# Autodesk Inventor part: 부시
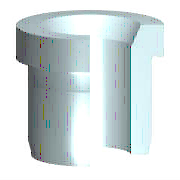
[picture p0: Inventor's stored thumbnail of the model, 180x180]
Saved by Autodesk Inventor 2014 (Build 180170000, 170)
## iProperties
IsCustomPart: 1
Created: 2009-02
Part Number: 부시
Material: 강, 연강
Description: 압력 맞춤 부시 - 머리 있는 유형
Document SubType Name: Modeling
Standard: ISO 4247
Designer: KYOUNG IL JANG
Standard Revision: 1판 1977-12-15
Standards Organization: ISO
Language: ko-KR
Size Designation: 15
Categories: <MemberInstance><Categories><Category DisplayName="기타 부품" InternalName="5aa15e00-363f-49f2-933f-16f664388e3f" Mnemonic="OTHER"><Category DisplayName="드릴 부싱" Int
Density: 7.86 g/cm^3
Mass: 62.5871 g
Surface Area: 38.4072 cm^2
Volume: 7.96273 cm^3
Appearance: 강철
Author: KYOUNG IL JANG
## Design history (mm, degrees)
revolve "본체" stored, may be unused: angle "d12" = 90 deg
body "Solid1"
chamfer "모따기1" distance "d13" = 2 (= KAH); stored, may be unused: angle "d14" = 30 deg (= SEWI), second distance "d19" = 2 (= KAH)
chamfer "모따기2" distance "d15" = 1.5 (= PHH); stored, may be unused: angle "d16" = 15 deg (= ANG), second distance "d20" = 1.5 (= PHH)
sketch "스케치1"
  geometry: L1 (2.5, 11)-(24, 11); L2 (24, 11)-(24, 6); L3 (24, 6)-(-4, 6); L4 (-4, 6)-(-4, 13); L5 (-4, 13)-(0, 13); L6 (0, 13)-(0, 12.304); L7 (-2.619, 0)-(24, 0); L8 (0, 12.304)-(-0.187, 11.425); L9 (2.5, 11)-(1.457, 10.72); L10 (0.4, 10.7)-(1.301, 10.7); L11 (-6.4, 0)-(10.4, 0) reference; L12 (0, -2.2)-(0, 13.2) reference; A1 r 0.6 centre (1.301, 11.3) between (1.301, 10.7) and (1.457, 10.72); A2 r 0.6 centre (0.4, 11.3) between (-0.187, 11.425) and (0.4, 10.7)
  constraints: 20 end point, 5 parallel, 4 point on circle, 4 tangent, 2 centre point, 2 collinear, 2 perpendicular, 1 horizontal, 1 point on line
  dimensions: "d0" = 15 deg angle of L1 L9; "d1" = 12 deg angle of L6 L8; "d2" = 0.6 radius of A2 (= FSRR); "d3" = 0.6 radius of A1 (= FSRR); "d4" = 0.3 distance between parallel lines of L1 L10 (= FST1); "d5" = 0.2 distance edge to line of A2 L6 (= FST2); "d6" = 2.5 distance from line of L1.start L6 (= FSB); "d7" = 12 diameter of L3 L7 (= NND); "d8" = 22 diameter of L1 L7 (= SD2); "d9" = 28 distance between parallel lines of L2 L4 (= NLG); "d10" = 4 distance of L4.end L5.end (= KOH); "d11" = 26 diameter of L5 L7 (= KOD)
other parameters: "NLG" = 28 [user parameter; used in 1 equation term], "NND" = 12 [user parameter; used in 1 equation term], "KOH" = 4 [user parameter; used in 1 equation term], "KOD" = 26 [user parameter; used in 1 equation term], "KAH" = 2 [user parameter; used in 2 equation terms], "SEWI" = 30 deg [user parameter; used in 1 equation term], "ANG" = 15 deg [user parameter; used in 1 equation term], "PHH" = 1.5 [user parameter; used in 2 equation terms], "FST1" = 0.3 [user parameter; used in 1 equation term], "FST2" = 0.2 [user parameter; used in 1 equation term], "FSB" = 2.5 [user parameter; used in 1 equation term], "FSRR" = 0.6 [user parameter; used in 2 equation terms], "SD2" = 22 [user parameter; used in 1 equation term], "d17" = 0, "d18" = 0, "NNDMIN" = 12 [user parameter], "FSH" = 2.1 [user parameter], "NNDMAX" = 15 [user parameter]
